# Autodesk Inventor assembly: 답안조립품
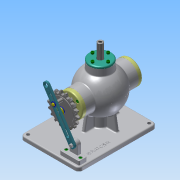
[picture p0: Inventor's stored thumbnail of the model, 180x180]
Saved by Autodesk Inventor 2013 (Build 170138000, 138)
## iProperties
Created: 2017-07
Part Number: 답안조립품
Document SubType Name: Assembly
Designer: Administrator
Mass: 3277.44 g
Surface Area: 2432.27 cm^2
Volume: 944.508 cm^3
Density: 3.47 g/cm^3
Author: Administrator
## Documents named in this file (20)
- C:\Users\Administrator\Desktop\370708V1006\답안조립품.iam
- C:\Users\Administrator\Desktop\370708V1006\본체.ipt
- C:\Users\Administrator\Desktop\370708V1006\본체커버.ipt
- C:\Users\Administrator\Desktop\370708V1006\베어링 6202.ipt
- C:\Users\Administrator\Desktop\370708V1006\뒤커버.ipt
- C:\Users\Administrator\Desktop\370708V1006\볼트 M4x12.ipt
- C:\Users\Administrator\Desktop\370708V1006\축.ipt
- C:\Users\Administrator\Desktop\370708V1006\앞커버.ipt
- C:\Users\Administrator\Desktop\370708V1006\오일실.ipt
- C:\Users\Administrator\Desktop\370708V1006\키 3 x 3 x 12.ipt
- C:\Users\Administrator\Desktop\370708V1006\슬라이드.ipt
- C:\Users\Administrator\Desktop\370708V1006\슬라이드 커버.ipt
- C:\Users\Administrator\Desktop\370708V1006\고정핀.ipt
- C:\Users\Administrator\Desktop\370708V1006\스프로킷.ipt
- C:\Users\Administrator\Desktop\370708V1006\연결대.ipt
- C:\Users\Administrator\Desktop\370708V1006\와셔 8x17.ipt
- C:\Users\Administrator\Desktop\370708V1006\너트 M8x1.ipt
- C:\Users\Administrator\Desktop\370708V1006\둥근머리 볼트 M4x8.ipt
- C:\Users\Administrator\Desktop\370708V1006\와셔 ISO 7093 A.ipt
- C:\Users\Administrator\Desktop\370708V1006\스프링.ipt
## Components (1 placed, 1 different names)
1. 고정핀:1 — 각도:5, 각도:6
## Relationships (2: Angle 2)
- 각도:5 [Angle]: 고정핀:1
- 각도:6 [Angle]: 고정핀:1
